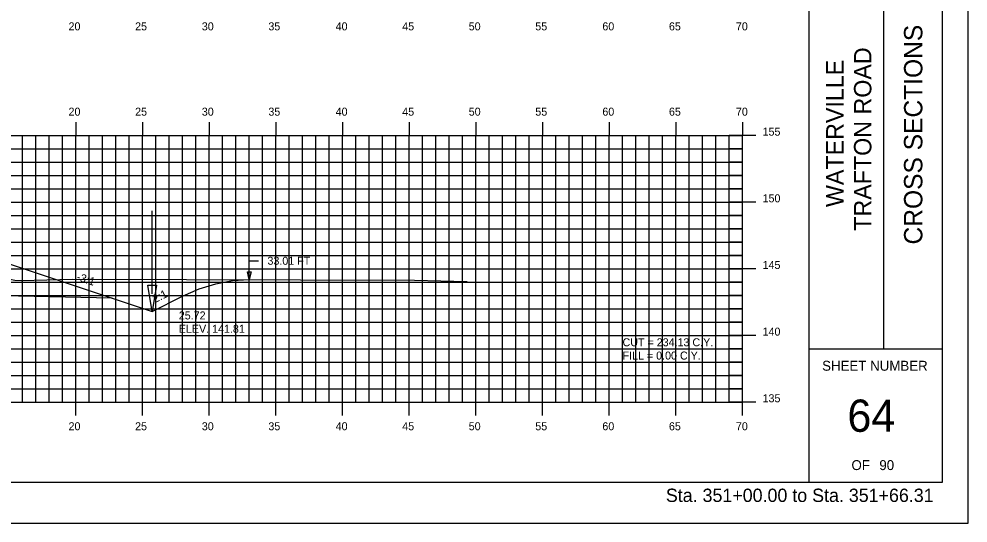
# Model space of a CAD drawing. Extents: x 1144751 to 1144921, y 608981 to 609091.
# Drawn here: x 1144849.4 to 1144920.5, y 608981.3 to 609019.1 of the extents above; entities that cross this region are included whole.
import ezdxf

# ---------------------------------------------------------------- set-up
doc = ezdxf.new("R2010")
doc.units = 0
for name, color, linetype in [('ANNOTATION', 7, 'Continuous'), ('BORDER', 7, 'Continuous'), ('D_Drainage_Ditch_Line', 7, 'Continuous'), ('D_Roadway_SlopeLines', 7, 'Continuous'), ('D_Roadway_SubGrade', 7, 'Continuous'), ('D_Text_Standard', 7, 'Continuous'), ('H_V ANNOTATION', 7, 'Continuous'), ('HIGHWAY_TITLE', 7, 'Continuous'), ('MAJOR', 7, 'Continuous'), ('MINOR', 7, 'Continuous'), ('PLOT BOUNDARY', 7, 'Continuous'), ('S_Roadway_Centerline', 7, 'Continuous')]:
    doc.layers.add(name, color=color, linetype=linetype)

msp = doc.modelspace()

# ---------------------------------------------------------------- linework, layer by layer
msp.add_lwpolyline([(1144797.455, 609001.234), (1144798.705, 609001.105), (1144799.955, 609000.834), (1144801.205, 609000.422), (1144802.455, 608999.868), (1144807.894, 608997.148), (1144810.894, 608998.148), (1144818.618, 609000.723), (1144818.619, 609000.723), (1144822.619, 609000.883), (1144833.619, 609001.103), (1144844.619, 609000.883), (1144848.619, 609000.723), (1144856.342, 608998.148), (1144859.342, 608997.148), (1144861.625, 608998.29), (1144862.875, 608998.836), (1144864.125, 608999.226), (1144865.375, 608999.458), (1144866.625, 608999.533)])
at = {"layer": 'BORDER'}
for p, q in [((1144908.619, 608984.335), (1144908.619, 609089.335)), ((1144914.21, 608994.338), (1144914.21, 609029.338)), ((1144908.619, 608994.338), (1144918.619, 608994.338))]:
    msp.add_line(p, q, dxfattribs=at)
msp.add_lwpolyline([(1144758.619, 608984.335), (1144918.619, 608984.335), (1144918.619, 609089.335), (1144758.619, 609089.335)], close=True, dxfattribs=at)
at = {"layer": 'D_Drainage_Ditch_Line'}
msp.add_line((1144859.342, 608998.461), (1144859.343, 609004.704), dxfattribs=at)
msp.add_lwpolyline([(1144859.014, 608999.117), (1144859.67, 608999.117), (1144859.342, 608997.148)], close=True, dxfattribs=at)
at = {"layer": 'D_Roadway_SlopeLines'}
for points in [[(1144859.342, 608997.148), (1144861.625, 608998.29), (1144862.875, 608998.836), (1144864.125, 608999.226), (1144865.375, 608999.458), (1144866.625, 608999.533)], [(1144856.342, 608998.148), (1144859.342, 608997.148)]]:
    msp.add_lwpolyline(points, dxfattribs=at)
at = {"layer": 'D_Roadway_SubGrade'}
msp.add_lwpolyline([(1144844.619, 609000.466), (1144844.619, 609000.633), (1144848.619, 609000.473), (1144848.619, 609000.723), (1144848.619, 609000.723), (1144856.342, 608998.148), (1144844.619, 608998.383)], close=True, dxfattribs=at)
at = {"layer": 'D_Text_Standard'}
msp.add_lwpolyline([(1144866.625, 608999.54), (1144866.63, 609000.951), (1144867.31, 609000.951)], dxfattribs=at)
msp.add_lwpolyline([(1144866.625, 608999.54), (1144866.482, 609000.122), (1144866.773, 609000.121)], close=True, dxfattribs=at)
at = {"layer": 'MAJOR'}
for p, q in [((1144853.619, 609011.337), (1144853.619, 609010.335)), ((1144858.619, 609011.337), (1144858.619, 609010.335)), ((1144863.619, 609011.337), (1144863.619, 609010.335)), ((1144868.619, 609011.337), (1144868.619, 609010.335)), ((1144873.619, 609011.337), (1144873.619, 609010.335)), ((1144878.619, 609011.337), (1144878.619, 609010.335)), ((1144883.619, 609011.337), (1144883.619, 609010.335)), ((1144888.619, 609011.337), (1144888.619, 609010.335)), ((1144893.619, 609011.337), (1144893.619, 609010.335)), ((1144898.619, 609011.337), (1144898.619, 609010.335)), ((1144903.619, 609011.337), (1144903.619, 609010.335)), ((1144763.619, 609010.335), (1144903.619, 609010.335)), ((1144763.619, 609010.335), (1144903.619, 609010.335)), ((1144853.619, 608990.335), (1144853.619, 609010.335)), ((1144858.619, 608990.335), (1144858.619, 609010.335)), ((1144863.619, 608990.335), (1144863.619, 609010.335)), ((1144868.619, 608990.335), (1144868.619, 609010.335)), ((1144873.619, 608990.335), (1144873.619, 609010.335)), ((1144878.619, 608990.335), (1144878.619, 609010.335)), ((1144883.619, 608990.335), (1144883.619, 609010.335)), ((1144888.619, 608990.335), (1144888.619, 609010.335)), ((1144893.619, 608990.335), (1144893.619, 609010.335)), ((1144898.619, 608990.335), (1144898.619, 609010.335)), ((1144904.621, 609010.335), (1144902.617, 609010.335)), ((1144903.619, 608990.335), (1144903.619, 609010.335)), ((1144903.619, 608990.335), (1144903.619, 609010.335)), ((1144763.619, 609005.335), (1144903.619, 609005.335)), ((1144904.621, 609005.335), (1144902.617, 609005.335)), ((1144763.619, 609000.335), (1144903.619, 609000.335)), ((1144904.621, 609000.335), (1144902.617, 609000.335)), ((1144763.619, 608995.335), (1144903.619, 608995.335)), ((1144904.621, 608995.335), (1144902.617, 608995.335)), ((1144763.619, 608990.335), (1144903.619, 608990.335)), ((1144763.619, 608990.335), (1144903.619, 608990.335)), ((1144853.619, 608989.333), (1144853.619, 608990.335)), ((1144858.619, 608989.333), (1144858.619, 608990.335)), ((1144863.619, 608989.333), (1144863.619, 608990.335)), ((1144868.619, 608989.333), (1144868.619, 608990.335)), ((1144873.619, 608989.333), (1144873.619, 608990.335)), ((1144878.619, 608989.333), (1144878.619, 608990.335)), ((1144883.619, 608989.333), (1144883.619, 608990.335)), ((1144888.619, 608989.333), (1144888.619, 608990.335)), ((1144893.619, 608989.333), (1144893.619, 608990.335)), ((1144898.619, 608989.333), (1144898.619, 608990.335)), ((1144904.621, 608990.335), (1144902.617, 608990.335)), ((1144903.619, 608989.333), (1144903.619, 608990.335))]:
    msp.add_line(p, q, dxfattribs=at)
at = {"layer": 'MINOR'}
for p, q in [((1144849.619, 608990.335), (1144849.619, 609010.335)), ((1144850.619, 608990.335), (1144850.619, 609010.335)), ((1144851.619, 608990.335), (1144851.619, 609010.335)), ((1144852.619, 608990.335), (1144852.619, 609010.335)), ((1144854.619, 608990.335), (1144854.619, 609010.335)), ((1144855.619, 608990.335), (1144855.619, 609010.335)), ((1144856.619, 608990.335), (1144856.619, 609010.335)), ((1144857.619, 608990.335), (1144857.619, 609010.335)), ((1144859.619, 608990.335), (1144859.619, 609010.335)), ((1144860.619, 608990.335), (1144860.619, 609010.335)), ((1144861.619, 608990.335), (1144861.619, 609010.335)), ((1144862.619, 608990.335), (1144862.619, 609010.335)), ((1144864.619, 608990.335), (1144864.619, 609010.335)), ((1144865.619, 608990.335), (1144865.619, 609010.335)), ((1144866.619, 608990.335), (1144866.619, 609010.335)), ((1144867.619, 608990.335), (1144867.619, 609010.335)), ((1144869.619, 608990.335), (1144869.619, 609010.335)), ((1144870.619, 608990.335), (1144870.619, 609010.335)), ((1144871.619, 608990.335), (1144871.619, 609010.335)), ((1144872.619, 608990.335), (1144872.619, 609010.335)), ((1144874.619, 608990.335), (1144874.619, 609010.335)), ((1144875.619, 608990.335), (1144875.619, 609010.335)), ((1144876.619, 608990.335), (1144876.619, 609010.335)), ((1144877.619, 608990.335), (1144877.619, 609010.335)), ((1144879.619, 608990.335), (1144879.619, 609010.335)), ((1144880.619, 608990.335), (1144880.619, 609010.335)), ((1144881.619, 608990.335), (1144881.619, 609010.335)), ((1144882.619, 608990.335), (1144882.619, 609010.335)), ((1144884.619, 608990.335), (1144884.619, 609010.335)), ((1144885.619, 608990.335), (1144885.619, 609010.335)), ((1144886.619, 608990.335), (1144886.619, 609010.335)), ((1144887.619, 608990.335), (1144887.619, 609010.335)), ((1144889.619, 608990.335), (1144889.619, 609010.335)), ((1144890.619, 608990.335), (1144890.619, 609010.335)), ((1144891.619, 608990.335), (1144891.619, 609010.335)), ((1144892.619, 608990.335), (1144892.619, 609010.335)), ((1144894.619, 608990.335), (1144894.619, 609010.335)), ((1144895.619, 608990.335), (1144895.619, 609010.335)), ((1144896.619, 608990.335), (1144896.619, 609010.335)), ((1144897.619, 608990.335), (1144897.619, 609010.335)), ((1144899.619, 608990.335), (1144899.619, 609010.335)), ((1144900.619, 608990.335), (1144900.619, 609010.335)), ((1144901.619, 608990.335), (1144901.619, 609010.335)), ((1144902.619, 608990.335), (1144902.619, 609010.335)), ((1144763.619, 609009.335), (1144903.619, 609009.335)), ((1144903.619, 609009.335), (1144902.617, 609009.335)), ((1144763.619, 609008.335), (1144903.619, 609008.335)), ((1144903.619, 609008.335), (1144902.617, 609008.335)), ((1144763.619, 609007.335), (1144903.619, 609007.335)), ((1144903.619, 609007.335), (1144902.617, 609007.335)), ((1144763.619, 609006.335), (1144903.619, 609006.335)), ((1144903.619, 609006.335), (1144902.617, 609006.335)), ((1144763.619, 609004.335), (1144903.619, 609004.335)), ((1144903.619, 609004.335), (1144902.617, 609004.335)), ((1144763.619, 609003.335), (1144903.619, 609003.335)), ((1144903.619, 609003.335), (1144902.617, 609003.335)), ((1144763.619, 609002.335), (1144903.619, 609002.335)), ((1144903.619, 609002.335), (1144902.617, 609002.335)), ((1144763.619, 609001.335), (1144903.619, 609001.335)), ((1144903.619, 609001.335), (1144902.617, 609001.335)), ((1144763.619, 608999.335), (1144903.619, 608999.335)), ((1144903.619, 608999.335), (1144902.617, 608999.335)), ((1144763.619, 608998.335), (1144903.619, 608998.335)), ((1144903.619, 608998.335), (1144902.617, 608998.335)), ((1144763.619, 608997.335), (1144903.619, 608997.335)), ((1144903.619, 608997.335), (1144902.617, 608997.335)), ((1144763.619, 608996.335), (1144903.619, 608996.335)), ((1144903.619, 608996.335), (1144902.617, 608996.335)), ((1144763.619, 608994.335), (1144903.619, 608994.335)), ((1144903.619, 608994.335), (1144902.617, 608994.335)), ((1144763.619, 608993.335), (1144903.619, 608993.335)), ((1144903.619, 608993.335), (1144902.617, 608993.335)), ((1144763.619, 608992.335), (1144903.619, 608992.335)), ((1144903.619, 608992.335), (1144902.617, 608992.335)), ((1144763.619, 608991.335), (1144903.619, 608991.335)), ((1144903.619, 608991.335), (1144902.617, 608991.335))]:
    msp.add_line(p, q, dxfattribs=at)
at = {"layer": 'PLOT BOUNDARY'}
msp.add_lwpolyline([(1144750.526, 608981.276), (1144920.526, 608981.276), (1144920.526, 609091.276), (1144750.526, 609091.276)], close=True, dxfattribs=at)
at = {"layer": 'S_Roadway_Centerline'}
msp.add_lwpolyline([(1144784.091, 609001.855), (1144804.815, 609000.892), (1144806.118, 609000.876), (1144806.664, 609000.752), (1144813.58, 608999.76), (1144813.762, 608999.807), (1144816.936, 609000.648), (1144817.059, 609000.66), (1144819.398, 609000.91), (1144820.085, 609000.917), (1144830.699, 609001.046), (1144841.624, 609000.698), (1144842.406, 609000.678), (1144842.648, 609000.652), (1144844.954, 609000.353), (1144845.157, 609000.264), (1144849.049, 608999.486), (1144849.52, 608999.482), (1144853.374, 608999.568), (1144879.018, 608999.501), (1144882.968, 608999.398)], dxfattribs=at)

# ---------------------------------------------------------------- texts
at = {"layer": 'ANNOTATION'}
for s, rotation, p in [('-3:1', 341.56521, (1144853.63, 608999.506)), ('2:1', 26.56505, (1144859.556, 608997.773))]:
    msp.add_text(s, height=0.6, rotation=rotation, dxfattribs=at).set_placement(p)
at = {"layer": 'BORDER'}
msp.add_text('CROSS SECTIONS', height=1.37787, rotation=90, dxfattribs=at).set_placement((1144917.104, 609002.172))
for s, height, p in [('SHEET NUMBER', 0.74527, (1144909.585, 608992.701)), ('64', 2.4194, (1144911.48, 608988.118)), ('OF', 0.7453, (1144911.786, 608985.248)), ('90', 0.7453, (1144913.876, 608985.248))]:
    msp.add_text(s, height=height, dxfattribs=at).set_placement(p)
at = {"layer": 'D_Text_Standard'}
for s, p in [('33.01 FT', (1144867.99, 609000.651)), ('25.72', (1144861.342, 608996.548)), ('ELEV. 141.81', (1144861.342, 608995.546)), ('CUT = 234.13 C.Y.', (1144894.619, 608994.535)), ('FILL = 0.00 C.Y.', (1144894.619, 608993.539))]:
    msp.add_text(s, height=0.6, dxfattribs=at).set_placement(p)
at = {"layer": 'H_V ANNOTATION'}
for s, height, p in [('20', 0.6, (1144853.073, 609018.235)), ('25', 0.6, (1144858.065, 609018.235)), ('30', 0.6, (1144863.068, 609018.235)), ('35', 0.6, (1144868.06, 609018.235)), ('40', 0.6, (1144873.105, 609018.235)), ('45', 0.6, (1144878.097, 609018.235)), ('50', 0.6, (1144883.084, 609018.235)), ('55', 0.6, (1144888.076, 609018.235)), ('60', 0.6, (1144893.105, 609018.235)), ('65', 0.6, (1144898.097, 609018.235)), ('70', 0.6, (1144903.121, 609018.235)), ('20', 0.6, (1144853.073, 609011.835)), ('25', 0.6, (1144858.065, 609011.835)), ('30', 0.6, (1144863.068, 609011.835)), ('35', 0.6, (1144868.06, 609011.835)), ('40', 0.6, (1144873.105, 609011.835)), ('45', 0.6, (1144878.097, 609011.835)), ('50', 0.6, (1144883.084, 609011.835)), ('55', 0.6, (1144888.076, 609011.835)), ('60', 0.6, (1144893.105, 609011.835)), ('65', 0.6, (1144898.097, 609011.835)), ('70', 0.6, (1144903.121, 609011.835)), ('155', 0.6, (1144905.119, 609010.335)), ('150', 0.6, (1144905.119, 609005.335)), ('145', 0.6, (1144905.119, 609000.335)), ('140', 0.6, (1144905.119, 608995.335)), ('135', 0.6, (1144905.119, 608990.335)), ('20', 0.6, (1144853.073, 608988.235)), ('25', 0.6, (1144858.065, 608988.235)), ('30', 0.6, (1144863.068, 608988.235)), ('35', 0.6, (1144868.06, 608988.235)), ('40', 0.6, (1144873.105, 608988.235)), ('45', 0.6, (1144878.097, 608988.235)), ('50', 0.6, (1144883.084, 608988.235)), ('55', 0.6, (1144888.076, 608988.235)), ('60', 0.6, (1144893.105, 608988.235)), ('65', 0.6, (1144898.097, 608988.235)), ('70', 0.6, (1144903.121, 608988.235)), ('Sta. 351+00.00 to Sta. 351+66.31', 1.0002, (1144897.867, 608982.855))]:
    msp.add_text(s, height=height, dxfattribs=at).set_placement(p)
at = {"layer": 'HIGHWAY_TITLE'}
for s, height, p in [('TRAFTON ROAD', 1.30428, (1144913.278, 609003.201)), ('WATERVILLE', 1.3043, (1144911.191, 609004.98))]:
    msp.add_text(s, height=height, rotation=90, dxfattribs=at).set_placement(p)

doc.saveas('drawing.dxf')
